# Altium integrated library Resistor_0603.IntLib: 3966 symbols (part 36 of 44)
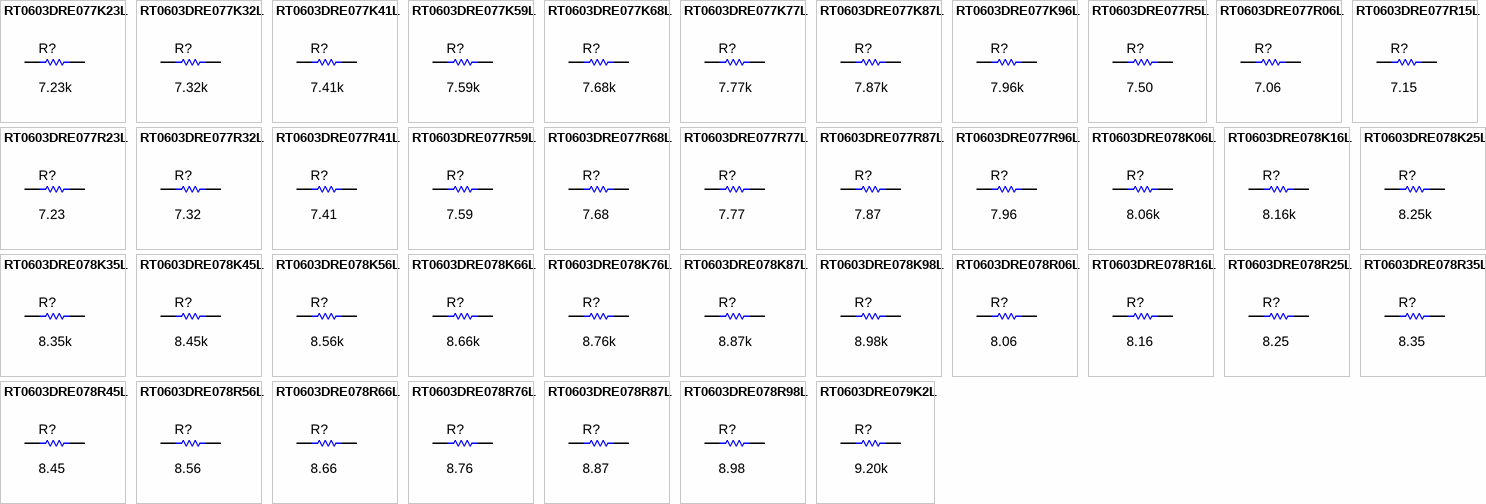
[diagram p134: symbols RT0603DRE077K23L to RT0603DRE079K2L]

## RT0603DRE078R87L
designator R?  ValueDisplayed: 8.87  (hidden comment: RT0603DRE078R87L)
RES, 8.87, 0.5%, 0.1 W, 0603; Manufacturer: Yageo America; CompType: Resistor; Value: 8.87; Value_Code: 8R87; Tolerance_%: 0.5; Power_W: 0.1; Value2: 0.1W; VDC_V: 75; TempCo: 50 ppm/C; SizeArea_mm2: 1.28; SizeX_mm: 1.6; SizeY_mm: 0.8; SizeZ_mm: 1; EIA_Code: E192; U/M: EA; AEC Category: Q200
signal-integrity model Resistor
simulation model Resistor
footprint 0603
footprint 0603M
footprint 0603L
footprint 0603_HV
footprint 0603S
pins: 1, 2

## RT0603DRE078R98L
designator R?  ValueDisplayed: 8.98  (hidden comment: RT0603DRE078R98L)
RES, 8.98, 0.5%, 0.1 W, 0603; Manufacturer: Yageo America; CompType: Resistor; Value: 8.98; Value_Code: 8R98; Tolerance_%: 0.5; Power_W: 0.1; Value2: 0.1W; VDC_V: 75; TempCo: 50 ppm/C; SizeArea_mm2: 1.28; SizeX_mm: 1.6; SizeY_mm: 0.8; SizeZ_mm: 1; EIA_Code: E192; U/M: EA; AEC Category: Q200
signal-integrity model Resistor
simulation model Resistor
footprint 0603
footprint 0603M
footprint 0603L
footprint 0603_HV
footprint 0603S
pins: 1, 2

## RT0603DRE079K2L
designator R?  ValueDisplayed: 9.20k  (hidden comment: RT0603DRE079K2L)
RES, 9.20 k, 0.5%, 0.1 W, 0603; Manufacturer: Yageo America; CompType: Resistor; Value: 9.20k; Res_ohm: 9200; Value_Code: 9k20; Tolerance_%: 0.5; Power_W: 0.1; Value2: 0.1W; VDC_V: 75; TempCo: 50 ppm/C; SizeArea_mm2: 1.28; SizeX_mm: 1.6; SizeY_mm: 0.8; SizeZ_mm: 1; EIA_Code: E192; U/M: EA; AEC Category: Q200
signal-integrity model Resistor
simulation model Resistor
footprint 0603
footprint 0603M
footprint 0603L
footprint 0603_HV
footprint 0603S
pins: 1, 2

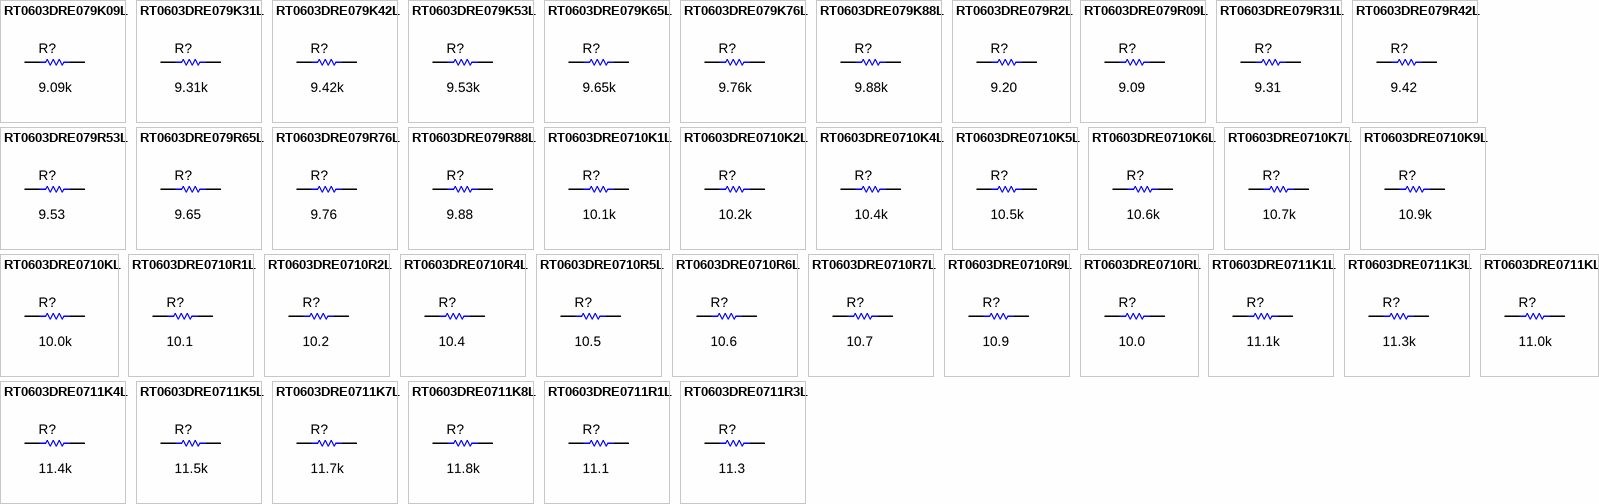
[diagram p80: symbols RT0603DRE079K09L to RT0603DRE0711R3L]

## RT0603DRE079K09L
designator R?  ValueDisplayed: 9.09k  (hidden comment: RT0603DRE079K09L)
RES, 9.09 k, 0.5%, 0.1 W, 0603; Manufacturer: Yageo America; CompType: Resistor; Value: 9.09k; Res_ohm: 9090; Value_Code: 9k09; Tolerance_%: 0.5; Power_W: 0.1; Value2: 0.1W; VDC_V: 75; TempCo: 50 ppm/C; SizeArea_mm2: 1.28; SizeX_mm: 1.6; SizeY_mm: 0.8; SizeZ_mm: 1; EIA_Code: E192; U/M: EA; AEC Category: Q200
signal-integrity model Resistor
simulation model Resistor
footprint 0603
footprint 0603M
footprint 0603L
footprint 0603_HV
footprint 0603S
pins: 1, 2

## RT0603DRE079K31L
designator R?  ValueDisplayed: 9.31k  (hidden comment: RT0603DRE079K31L)
RES, 9.31 k, 0.5%, 0.1 W, 0603; Manufacturer: Yageo America; CompType: Resistor; Value: 9.31k; Res_ohm: 9310; Value_Code: 9k31; Tolerance_%: 0.5; Power_W: 0.1; Value2: 0.1W; VDC_V: 75; TempCo: 50 ppm/C; SizeArea_mm2: 1.28; SizeX_mm: 1.6; SizeY_mm: 0.8; SizeZ_mm: 1; EIA_Code: E192; U/M: EA; AEC Category: Q200
signal-integrity model Resistor
simulation model Resistor
footprint 0603
footprint 0603M
footprint 0603L
footprint 0603_HV
footprint 0603S
pins: 1, 2

## RT0603DRE079K42L
designator R?  ValueDisplayed: 9.42k  (hidden comment: RT0603DRE079K42L)
RES, 9.42 k, 0.5%, 0.1 W, 0603; Manufacturer: Yageo America; CompType: Resistor; Value: 9.42k; Res_ohm: 9420; Value_Code: 9k42; Tolerance_%: 0.5; Power_W: 0.1; Value2: 0.1W; VDC_V: 75; TempCo: 50 ppm/C; SizeArea_mm2: 1.28; SizeX_mm: 1.6; SizeY_mm: 0.8; SizeZ_mm: 1; EIA_Code: E192; U/M: EA; AEC Category: Q200
signal-integrity model Resistor
simulation model Resistor
footprint 0603
footprint 0603M
footprint 0603L
footprint 0603_HV
footprint 0603S
pins: 1, 2

## RT0603DRE079K53L
designator R?  ValueDisplayed: 9.53k  (hidden comment: RT0603DRE079K53L)
RES, 9.53 k, 0.5%, 0.1 W, 0603; Manufacturer: Yageo America; CompType: Resistor; Value: 9.53k; Res_ohm: 9530; Value_Code: 9k53; Tolerance_%: 0.5; Power_W: 0.1; Value2: 0.1W; VDC_V: 75; TempCo: 50 ppm/C; SizeArea_mm2: 1.28; SizeX_mm: 1.6; SizeY_mm: 0.8; SizeZ_mm: 1; EIA_Code: E192; U/M: EA; AEC Category: Q200
signal-integrity model Resistor
simulation model Resistor
footprint 0603
footprint 0603M
footprint 0603L
footprint 0603_HV
footprint 0603S
pins: 1, 2

## RT0603DRE079K65L
designator R?  ValueDisplayed: 9.65k  (hidden comment: RT0603DRE079K65L)
RES, 9.65 k, 0.5%, 0.1 W, 0603; Manufacturer: Yageo America; CompType: Resistor; Value: 9.65k; Res_ohm: 9650; Value_Code: 9k65; Tolerance_%: 0.5; Power_W: 0.1; Value2: 0.1W; VDC_V: 75; TempCo: 50 ppm/C; SizeArea_mm2: 1.28; SizeX_mm: 1.6; SizeY_mm: 0.8; SizeZ_mm: 1; EIA_Code: E192; U/M: EA; AEC Category: Q200
signal-integrity model Resistor
simulation model Resistor
footprint 0603
footprint 0603M
footprint 0603L
footprint 0603_HV
footprint 0603S
pins: 1, 2

## RT0603DRE079K76L
designator R?  ValueDisplayed: 9.76k  (hidden comment: RT0603DRE079K76L)
RES, 9.76 k, 0.5%, 0.1 W, 0603; Manufacturer: Yageo America; CompType: Resistor; Value: 9.76k; Res_ohm: 9760; Value_Code: 9k76; Tolerance_%: 0.5; Power_W: 0.1; Value2: 0.1W; VDC_V: 75; TempCo: 50 ppm/C; SizeArea_mm2: 1.28; SizeX_mm: 1.6; SizeY_mm: 0.8; SizeZ_mm: 1; EIA_Code: E192; U/M: EA; AEC Category: Q200
signal-integrity model Resistor
simulation model Resistor
footprint 0603
footprint 0603M
footprint 0603L
footprint 0603_HV
footprint 0603S
pins: 1, 2

## RT0603DRE079K88L
designator R?  ValueDisplayed: 9.88k  (hidden comment: RT0603DRE079K88L)
RES, 9.88 k, 0.5%, 0.1 W, 0603; Manufacturer: Yageo America; CompType: Resistor; Value: 9.88k; Res_ohm: 9880; Value_Code: 9k88; Tolerance_%: 0.5; Power_W: 0.1; Value2: 0.1W; VDC_V: 75; TempCo: 50 ppm/C; SizeArea_mm2: 1.28; SizeX_mm: 1.6; SizeY_mm: 0.8; SizeZ_mm: 1; EIA_Code: E192; U/M: EA; AEC Category: Q200
signal-integrity model Resistor
simulation model Resistor
footprint 0603
footprint 0603M
footprint 0603L
footprint 0603_HV
footprint 0603S
pins: 1, 2

## RT0603DRE079R2L
designator R?  ValueDisplayed: 9.20  (hidden comment: RT0603DRE079R2L)
RES, 9.20, 0.5%, 0.1 W, 0603; Manufacturer: Yageo America; CompType: Resistor; Value: 9.20; Res_ohm: 9.2; Value_Code: 9R20; Tolerance_%: 0.5; Power_W: 0.1; Value2: 0.1W; VDC_V: 75; TempCo: 50 ppm/C; SizeArea_mm2: 1.28; SizeX_mm: 1.6; SizeY_mm: 0.8; SizeZ_mm: 1; EIA_Code: E192; U/M: EA; AEC Category: Q200
signal-integrity model Resistor
simulation model Resistor
footprint 0603
footprint 0603M
footprint 0603L
footprint 0603_HV
footprint 0603S
pins: 1, 2

## RT0603DRE079R09L
designator R?  ValueDisplayed: 9.09  (hidden comment: RT0603DRE079R09L)
RES, 9.09, 0.5%, 0.1 W, 0603; Manufacturer: Yageo America; CompType: Resistor; Value: 9.09; Value_Code: 9R09; Tolerance_%: 0.5; Power_W: 0.1; Value2: 0.1W; VDC_V: 75; TempCo: 50 ppm/C; SizeArea_mm2: 1.28; SizeX_mm: 1.6; SizeY_mm: 0.8; SizeZ_mm: 1; EIA_Code: E192; U/M: EA; AEC Category: Q200
signal-integrity model Resistor
simulation model Resistor
footprint 0603
footprint 0603M
footprint 0603L
footprint 0603_HV
footprint 0603S
pins: 1, 2

## RT0603DRE079R31L
designator R?  ValueDisplayed: 9.31  (hidden comment: RT0603DRE079R31L)
RES, 9.31, 0.5%, 0.1 W, 0603; Manufacturer: Yageo America; CompType: Resistor; Value: 9.31; Value_Code: 9R31; Tolerance_%: 0.5; Power_W: 0.1; Value2: 0.1W; VDC_V: 75; TempCo: 50 ppm/C; SizeArea_mm2: 1.28; SizeX_mm: 1.6; SizeY_mm: 0.8; SizeZ_mm: 1; EIA_Code: E192; U/M: EA; AEC Category: Q200
signal-integrity model Resistor
simulation model Resistor
footprint 0603
footprint 0603M
footprint 0603L
footprint 0603_HV
footprint 0603S
pins: 1, 2

## RT0603DRE079R42L
designator R?  ValueDisplayed: 9.42  (hidden comment: RT0603DRE079R42L)
RES, 9.42, 0.5%, 0.1 W, 0603; Manufacturer: Yageo America; CompType: Resistor; Value: 9.42; Value_Code: 9R42; Tolerance_%: 0.5; Power_W: 0.1; Value2: 0.1W; VDC_V: 75; TempCo: 50 ppm/C; SizeArea_mm2: 1.28; SizeX_mm: 1.6; SizeY_mm: 0.8; SizeZ_mm: 1; EIA_Code: E192; U/M: EA; AEC Category: Q200
signal-integrity model Resistor
simulation model Resistor
footprint 0603
footprint 0603M
footprint 0603L
footprint 0603_HV
footprint 0603S
pins: 1, 2

## RT0603DRE079R53L
designator R?  ValueDisplayed: 9.53  (hidden comment: RT0603DRE079R53L)
RES, 9.53, 0.5%, 0.1 W, 0603; Manufacturer: Yageo America; CompType: Resistor; Value: 9.53; Value_Code: 9R53; Tolerance_%: 0.5; Power_W: 0.1; Value2: 0.1W; VDC_V: 75; TempCo: 50 ppm/C; SizeArea_mm2: 1.28; SizeX_mm: 1.6; SizeY_mm: 0.8; SizeZ_mm: 1; EIA_Code: E192; U/M: EA; AEC Category: Q200
signal-integrity model Resistor
simulation model Resistor
footprint 0603
footprint 0603M
footprint 0603L
footprint 0603_HV
footprint 0603S
pins: 1, 2

## RT0603DRE079R65L
designator R?  ValueDisplayed: 9.65  (hidden comment: RT0603DRE079R65L)
RES, 9.65, 0.5%, 0.1 W, 0603; Manufacturer: Yageo America; CompType: Resistor; Value: 9.65; Value_Code: 9R65; Tolerance_%: 0.5; Power_W: 0.1; Value2: 0.1W; VDC_V: 75; TempCo: 50 ppm/C; SizeArea_mm2: 1.28; SizeX_mm: 1.6; SizeY_mm: 0.8; SizeZ_mm: 1; EIA_Code: E192; U/M: EA; AEC Category: Q200
signal-integrity model Resistor
simulation model Resistor
footprint 0603
footprint 0603M
footprint 0603L
footprint 0603_HV
footprint 0603S
pins: 1, 2

## RT0603DRE079R76L
designator R?  ValueDisplayed: 9.76  (hidden comment: RT0603DRE079R76L)
RES, 9.76, 0.5%, 0.1 W, 0603; Manufacturer: Yageo America; CompType: Resistor; Value: 9.76; Value_Code: 9R76; Tolerance_%: 0.5; Power_W: 0.1; Value2: 0.1W; VDC_V: 75; TempCo: 50 ppm/C; SizeArea_mm2: 1.28; SizeX_mm: 1.6; SizeY_mm: 0.8; SizeZ_mm: 1; EIA_Code: E192; U/M: EA; AEC Category: Q200
signal-integrity model Resistor
simulation model Resistor
footprint 0603
footprint 0603M
footprint 0603L
footprint 0603_HV
footprint 0603S
pins: 1, 2

## RT0603DRE079R88L
designator R?  ValueDisplayed: 9.88  (hidden comment: RT0603DRE079R88L)
RES, 9.88, 0.5%, 0.1 W, 0603; Manufacturer: Yageo America; CompType: Resistor; Value: 9.88; Value_Code: 9R88; Tolerance_%: 0.5; Power_W: 0.1; Value2: 0.1W; VDC_V: 75; TempCo: 50 ppm/C; SizeArea_mm2: 1.28; SizeX_mm: 1.6; SizeY_mm: 0.8; SizeZ_mm: 1; EIA_Code: E192; U/M: EA; AEC Category: Q200
signal-integrity model Resistor
simulation model Resistor
footprint 0603
footprint 0603M
footprint 0603L
footprint 0603_HV
footprint 0603S
pins: 1, 2

## RT0603DRE0710K1L
designator R?  ValueDisplayed: 10.1k  (hidden comment: RT0603DRE0710K1L)
RES, 10.1 k, 0.5%, 0.1 W, 0603; Manufacturer: Yageo America; CompType: Resistor; Value: 10.1k; Res_ohm: 10100; Value_Code: 10k1; Tolerance_%: 0.5; Power_W: 0.1; Value2: 0.1W; VDC_V: 75; TempCo: 50 ppm/C; SizeArea_mm2: 1.28; SizeX_mm: 1.6; SizeY_mm: 0.8; SizeZ_mm: 1; EIA_Code: E192; U/M: EA; AEC Category: Q200
signal-integrity model Resistor
simulation model Resistor
footprint 0603
footprint 0603M
footprint 0603L
footprint 0603_HV
footprint 0603S
pins: 1, 2

## RT0603DRE0710K2L
designator R?  ValueDisplayed: 10.2k  (hidden comment: RT0603DRE0710K2L)
RES, 10.2 k, 0.5%, 0.1 W, 0603; Manufacturer: Yageo America; CompType: Resistor; Value: 10.2k; Res_ohm: 10200; Value_Code: 10k2; Tolerance_%: 0.5; Power_W: 0.1; Value2: 0.1W; VDC_V: 75; TempCo: 50 ppm/C; SizeArea_mm2: 1.28; SizeX_mm: 1.6; SizeY_mm: 0.8; SizeZ_mm: 1; EIA_Code: E192; U/M: EA; AEC Category: Q200
signal-integrity model Resistor
simulation model Resistor
footprint 0603
footprint 0603M
footprint 0603L
footprint 0603_HV
footprint 0603S
pins: 1, 2

## RT0603DRE0710K4L
designator R?  ValueDisplayed: 10.4k  (hidden comment: RT0603DRE0710K4L)
RES, 10.4 k, 0.5%, 0.1 W, 0603; Manufacturer: Yageo America; CompType: Resistor; Value: 10.4k; Res_ohm: 10400; Value_Code: 10k4; Tolerance_%: 0.5; Power_W: 0.1; Value2: 0.1W; VDC_V: 75; TempCo: 50 ppm/C; SizeArea_mm2: 1.28; SizeX_mm: 1.6; SizeY_mm: 0.8; SizeZ_mm: 1; EIA_Code: E192; U/M: EA; AEC Category: Q200
signal-integrity model Resistor
simulation model Resistor
footprint 0603
footprint 0603M
footprint 0603L
footprint 0603_HV
footprint 0603S
pins: 1, 2

## RT0603DRE0710K5L
designator R?  ValueDisplayed: 10.5k  (hidden comment: RT0603DRE0710K5L)
RES, 10.5 k, 0.5%, 0.1 W, 0603; Manufacturer: Yageo America; CompType: Resistor; Value: 10.5k; Res_ohm: 10500; Value_Code: 10k5; Tolerance_%: 0.5; Power_W: 0.1; Value2: 0.1W; VDC_V: 75; TempCo: 50 ppm/C; SizeArea_mm2: 1.28; SizeX_mm: 1.6; SizeY_mm: 0.8; SizeZ_mm: 1; EIA_Code: E192; U/M: EA; AEC Category: Q200
signal-integrity model Resistor
simulation model Resistor
footprint 0603
footprint 0603M
footprint 0603L
footprint 0603_HV
footprint 0603S
pins: 1, 2

## RT0603DRE0710K6L
designator R?  ValueDisplayed: 10.6k  (hidden comment: RT0603DRE0710K6L)
RES, 10.6 k, 0.5%, 0.1 W, 0603; Manufacturer: Yageo America; CompType: Resistor; Value: 10.6k; Res_ohm: 10600; Value_Code: 10k6; Tolerance_%: 0.5; Power_W: 0.1; Value2: 0.1W; VDC_V: 75; TempCo: 50 ppm/C; SizeArea_mm2: 1.28; SizeX_mm: 1.6; SizeY_mm: 0.8; SizeZ_mm: 1; EIA_Code: E192; U/M: EA; AEC Category: Q200
signal-integrity model Resistor
simulation model Resistor
footprint 0603
footprint 0603M
footprint 0603L
footprint 0603_HV
footprint 0603S
pins: 1, 2

## RT0603DRE0710K7L
designator R?  ValueDisplayed: 10.7k  (hidden comment: RT0603DRE0710K7L)
RES, 10.7 k, 0.5%, 0.1 W, 0603; Manufacturer: Yageo America; CompType: Resistor; Value: 10.7k; Res_ohm: 10700; Value_Code: 10k7; Tolerance_%: 0.5; Power_W: 0.1; Value2: 0.1W; VDC_V: 75; TempCo: 50 ppm/C; SizeArea_mm2: 1.28; SizeX_mm: 1.6; SizeY_mm: 0.8; SizeZ_mm: 1; EIA_Code: E192; U/M: EA; AEC Category: Q200
signal-integrity model Resistor
simulation model Resistor
footprint 0603
footprint 0603M
footprint 0603L
footprint 0603_HV
footprint 0603S
pins: 1, 2

## RT0603DRE0710K9L
designator R?  ValueDisplayed: 10.9k  (hidden comment: RT0603DRE0710K9L)
RES, 10.9 k, 0.5%, 0.1 W, 0603; Manufacturer: Yageo America; CompType: Resistor; Value: 10.9k; Res_ohm: 10900; Value_Code: 10k9; Tolerance_%: 0.5; Power_W: 0.1; Value2: 0.1W; VDC_V: 75; TempCo: 50 ppm/C; SizeArea_mm2: 1.28; SizeX_mm: 1.6; SizeY_mm: 0.8; SizeZ_mm: 1; EIA_Code: E192; U/M: EA; AEC Category: Q200
signal-integrity model Resistor
simulation model Resistor
footprint 0603
footprint 0603M
footprint 0603L
footprint 0603_HV
footprint 0603S
pins: 1, 2

## RT0603DRE0710KL
designator R?  ValueDisplayed: 10.0k  (hidden comment: RT0603DRE0710KL)
RES, 10.0 k, 0.5%, 0.1 W, 0603; Manufacturer: Yageo America; CompType: Resistor; Value: 10.0k; Res_ohm: 10000; Value_Code: 10k0; Tolerance_%: 0.5; Power_W: 0.1; Value2: 0.1W; VDC_V: 75; TempCo: 50 ppm/C; SizeArea_mm2: 1.28; SizeX_mm: 1.6; SizeY_mm: 0.8; SizeZ_mm: 1; EIA_Code: E192; U/M: EA; AEC Category: Q200; Green_Lifecycle: Active; Green_REACh: Passed
signal-integrity model Resistor
simulation model Resistor
footprint 0603
footprint 0603M
footprint 0603L
footprint 0603_HV
footprint 0603S
pins: 1, 2

## RT0603DRE0710R1L
designator R?  ValueDisplayed: 10.1  (hidden comment: RT0603DRE0710R1L)
RES, 10.1, 0.5%, 0.1 W, 0603; Manufacturer: Yageo America; CompType: Resistor; Value: 10.1; Value_Code: 10R1; Tolerance_%: 0.5; Power_W: 0.1; Value2: 0.1W; VDC_V: 75; TempCo: 50 ppm/C; SizeArea_mm2: 1.28; SizeX_mm: 1.6; SizeY_mm: 0.8; SizeZ_mm: 1; EIA_Code: E192; U/M: EA; AEC Category: Q200
signal-integrity model Resistor
simulation model Resistor
footprint 0603
footprint 0603M
footprint 0603L
footprint 0603_HV
footprint 0603S
pins: 1, 2

## RT0603DRE0710R2L
designator R?  ValueDisplayed: 10.2  (hidden comment: RT0603DRE0710R2L)
RES, 10.2, 0.5%, 0.1 W, 0603; Manufacturer: Yageo America; CompType: Resistor; Value: 10.2; Value_Code: 10R2; Tolerance_%: 0.5; Power_W: 0.1; Value2: 0.1W; VDC_V: 75; TempCo: 50 ppm/C; SizeArea_mm2: 1.28; SizeX_mm: 1.6; SizeY_mm: 0.8; SizeZ_mm: 1; EIA_Code: E192; U/M: EA; AEC Category: Q200
signal-integrity model Resistor
simulation model Resistor
footprint 0603
footprint 0603M
footprint 0603L
footprint 0603_HV
footprint 0603S
pins: 1, 2

## RT0603DRE0710R4L
designator R?  ValueDisplayed: 10.4  (hidden comment: RT0603DRE0710R4L)
RES, 10.4, 0.5%, 0.1 W, 0603; Manufacturer: Yageo America; CompType: Resistor; Value: 10.4; Value_Code: 10R4; Tolerance_%: 0.5; Power_W: 0.1; Value2: 0.1W; VDC_V: 75; TempCo: 50 ppm/C; SizeArea_mm2: 1.28; SizeX_mm: 1.6; SizeY_mm: 0.8; SizeZ_mm: 1; EIA_Code: E192; U/M: EA; AEC Category: Q200
signal-integrity model Resistor
simulation model Resistor
footprint 0603
footprint 0603M
footprint 0603L
footprint 0603_HV
footprint 0603S
pins: 1, 2

## RT0603DRE0710R5L
designator R?  ValueDisplayed: 10.5  (hidden comment: RT0603DRE0710R5L)
RES, 10.5, 0.5%, 0.1 W, 0603; Manufacturer: Yageo America; CompType: Resistor; Value: 10.5; Value_Code: 10R5; Tolerance_%: 0.5; Power_W: 0.1; Value2: 0.1W; VDC_V: 75; TempCo: 50 ppm/C; SizeArea_mm2: 1.28; SizeX_mm: 1.6; SizeY_mm: 0.8; SizeZ_mm: 1; EIA_Code: E192; U/M: EA; AEC Category: Q200
signal-integrity model Resistor
simulation model Resistor
footprint 0603
footprint 0603M
footprint 0603L
footprint 0603_HV
footprint 0603S
pins: 1, 2

## RT0603DRE0710R6L
designator R?  ValueDisplayed: 10.6  (hidden comment: RT0603DRE0710R6L)
RES, 10.6, 0.5%, 0.1 W, 0603; Manufacturer: Yageo America; CompType: Resistor; Value: 10.6; Value_Code: 10R6; Tolerance_%: 0.5; Power_W: 0.1; Value2: 0.1W; VDC_V: 75; TempCo: 50 ppm/C; SizeArea_mm2: 1.28; SizeX_mm: 1.6; SizeY_mm: 0.8; SizeZ_mm: 1; EIA_Code: E192; U/M: EA; AEC Category: Q200
signal-integrity model Resistor
simulation model Resistor
footprint 0603
footprint 0603M
footprint 0603L
footprint 0603_HV
footprint 0603S
pins: 1, 2

## RT0603DRE0710R7L
designator R?  ValueDisplayed: 10.7  (hidden comment: RT0603DRE0710R7L)
RES, 10.7, 0.5%, 0.1 W, 0603; Manufacturer: Yageo America; CompType: Resistor; Value: 10.7; Value_Code: 10R7; Tolerance_%: 0.5; Power_W: 0.1; Value2: 0.1W; VDC_V: 75; TempCo: 50 ppm/C; SizeArea_mm2: 1.28; SizeX_mm: 1.6; SizeY_mm: 0.8; SizeZ_mm: 1; EIA_Code: E192; U/M: EA; AEC Category: Q200
signal-integrity model Resistor
simulation model Resistor
footprint 0603
footprint 0603M
footprint 0603L
footprint 0603_HV
footprint 0603S
pins: 1, 2

## RT0603DRE0710R9L
designator R?  ValueDisplayed: 10.9  (hidden comment: RT0603DRE0710R9L)
RES, 10.9, 0.5%, 0.1 W, 0603; Manufacturer: Yageo America; CompType: Resistor; Value: 10.9; Value_Code: 10R9; Tolerance_%: 0.5; Power_W: 0.1; Value2: 0.1W; VDC_V: 75; TempCo: 50 ppm/C; SizeArea_mm2: 1.28; SizeX_mm: 1.6; SizeY_mm: 0.8; SizeZ_mm: 1; EIA_Code: E192; U/M: EA; AEC Category: Q200
signal-integrity model Resistor
simulation model Resistor
footprint 0603
footprint 0603M
footprint 0603L
footprint 0603_HV
footprint 0603S
pins: 1, 2

## RT0603DRE0710RL
designator R?  ValueDisplayed: 10.0  (hidden comment: RT0603DRE0710RL)
RES, 10.0, 0.5%, 0.1 W, 0603; Manufacturer: Yageo America; CompType: Resistor; Value: 10.0; Res_ohm: 10; Value_Code: 10R0; Tolerance_%: 0.5; Power_W: 0.1; Value2: 0.1W; VDC_V: 75; TempCo: 50 ppm/C; SizeArea_mm2: 1.28; SizeX_mm: 1.6; SizeY_mm: 0.8; SizeZ_mm: 1; EIA_Code: E192; U/M: EA; AEC Category: Q200
signal-integrity model Resistor
simulation model Resistor
footprint 0603
footprint 0603M
footprint 0603L
footprint 0603_HV
footprint 0603S
pins: 1, 2

## RT0603DRE0711K1L
designator R?  ValueDisplayed: 11.1k  (hidden comment: RT0603DRE0711K1L)
RES, 11.1 k, 0.5%, 0.1 W, 0603; Manufacturer: Yageo America; CompType: Resistor; Value: 11.1k; Res_ohm: 11100; Value_Code: 11k1; Tolerance_%: 0.5; Power_W: 0.1; Value2: 0.1W; VDC_V: 75; TempCo: 50 ppm/C; SizeArea_mm2: 1.28; SizeX_mm: 1.6; SizeY_mm: 0.8; SizeZ_mm: 1; EIA_Code: E192; U/M: EA; AEC Category: Q200
signal-integrity model Resistor
simulation model Resistor
footprint 0603
footprint 0603M
footprint 0603L
footprint 0603_HV
footprint 0603S
pins: 1, 2

## RT0603DRE0711K3L
designator R?  ValueDisplayed: 11.3k  (hidden comment: RT0603DRE0711K3L)
RES, 11.3 k, 0.5%, 0.1 W, 0603; Manufacturer: Yageo America; CompType: Resistor; Value: 11.3k; Res_ohm: 11300; Value_Code: 11k3; Tolerance_%: 0.5; Power_W: 0.1; Value2: 0.1W; VDC_V: 75; TempCo: 50 ppm/C; SizeArea_mm2: 1.28; SizeX_mm: 1.6; SizeY_mm: 0.8; SizeZ_mm: 1; EIA_Code: E192; U/M: EA; AEC Category: Q200
signal-integrity model Resistor
simulation model Resistor
footprint 0603
footprint 0603M
footprint 0603L
footprint 0603_HV
footprint 0603S
pins: 1, 2

## RT0603DRE0711K4L
designator R?  ValueDisplayed: 11.4k  (hidden comment: RT0603DRE0711K4L)
RES, 11.4 k, 0.5%, 0.1 W, 0603; Manufacturer: Yageo America; CompType: Resistor; Value: 11.4k; Res_ohm: 11400; Value_Code: 11k4; Tolerance_%: 0.5; Power_W: 0.1; Value2: 0.1W; VDC_V: 75; TempCo: 50 ppm/C; SizeArea_mm2: 1.28; SizeX_mm: 1.6; SizeY_mm: 0.8; SizeZ_mm: 1; EIA_Code: E192; U/M: EA; AEC Category: Q200
signal-integrity model Resistor
simulation model Resistor
footprint 0603
footprint 0603M
footprint 0603L
footprint 0603_HV
footprint 0603S
pins: 1, 2

## RT0603DRE0711K5L
designator R?  ValueDisplayed: 11.5k  (hidden comment: RT0603DRE0711K5L)
RES, 11.5 k, 0.5%, 0.1 W, 0603; Manufacturer: Yageo America; CompType: Resistor; Value: 11.5k; Res_ohm: 11500; Value_Code: 11k5; Tolerance_%: 0.5; Power_W: 0.1; Value2: 0.1W; VDC_V: 75; TempCo: 50 ppm/C; SizeArea_mm2: 1.28; SizeX_mm: 1.6; SizeY_mm: 0.8; SizeZ_mm: 1; EIA_Code: E192; U/M: EA; AEC Category: Q200
signal-integrity model Resistor
simulation model Resistor
footprint 0603
footprint 0603M
footprint 0603L
footprint 0603_HV
footprint 0603S
pins: 1, 2

## RT0603DRE0711K7L
designator R?  ValueDisplayed: 11.7k  (hidden comment: RT0603DRE0711K7L)
RES, 11.7 k, 0.5%, 0.1 W, 0603; Manufacturer: Yageo America; CompType: Resistor; Value: 11.7k; Res_ohm: 11700; Value_Code: 11k7; Tolerance_%: 0.5; Power_W: 0.1; Value2: 0.1W; VDC_V: 75; TempCo: 50 ppm/C; SizeArea_mm2: 1.28; SizeX_mm: 1.6; SizeY_mm: 0.8; SizeZ_mm: 1; EIA_Code: E192; U/M: EA; AEC Category: Q200
signal-integrity model Resistor
simulation model Resistor
footprint 0603
footprint 0603M
footprint 0603L
footprint 0603_HV
footprint 0603S
pins: 1, 2

## RT0603DRE0711K8L
designator R?  ValueDisplayed: 11.8k  (hidden comment: RT0603DRE0711K8L)
RES, 11.8 k, 0.5%, 0.1 W, 0603; Manufacturer: Yageo America; CompType: Resistor; Value: 11.8k; Res_ohm: 11800; Value_Code: 11k8; Tolerance_%: 0.5; Power_W: 0.1; Value2: 0.1W; VDC_V: 75; TempCo: 50 ppm/C; SizeArea_mm2: 1.28; SizeX_mm: 1.6; SizeY_mm: 0.8; SizeZ_mm: 1; EIA_Code: E192; U/M: EA; AEC Category: Q200
signal-integrity model Resistor
simulation model Resistor
footprint 0603
footprint 0603M
footprint 0603L
footprint 0603_HV
footprint 0603S
pins: 1, 2

## RT0603DRE0711KL
designator R?  ValueDisplayed: 11.0k  (hidden comment: RT0603DRE0711KL)
RES, 11.0 k, 0.5%, 0.1 W, 0603; Manufacturer: Yageo America; CompType: Resistor; Value: 11.0k; Res_ohm: 11000; Value_Code: 11k0; Tolerance_%: 0.5; Power_W: 0.1; Value2: 0.1W; VDC_V: 75; TempCo: 50 ppm/C; SizeArea_mm2: 1.28; SizeX_mm: 1.6; SizeY_mm: 0.8; SizeZ_mm: 1; EIA_Code: E192; U/M: EA; AEC Category: Q200
signal-integrity model Resistor
simulation model Resistor
footprint 0603
footprint 0603M
footprint 0603L
footprint 0603_HV
footprint 0603S
pins: 1, 2

## RT0603DRE0711R1L
designator R?  ValueDisplayed: 11.1  (hidden comment: RT0603DRE0711R1L)
RES, 11.1, 0.5%, 0.1 W, 0603; Manufacturer: Yageo America; CompType: Resistor; Value: 11.1; Value_Code: 11R1; Tolerance_%: 0.5; Power_W: 0.1; Value2: 0.1W; VDC_V: 75; TempCo: 50 ppm/C; SizeArea_mm2: 1.28; SizeX_mm: 1.6; SizeY_mm: 0.8; SizeZ_mm: 1; EIA_Code: E192; U/M: EA; AEC Category: Q200
signal-integrity model Resistor
simulation model Resistor
footprint 0603
footprint 0603M
footprint 0603L
footprint 0603_HV
footprint 0603S
pins: 1, 2

## RT0603DRE0711R3L
designator R?  ValueDisplayed: 11.3  (hidden comment: RT0603DRE0711R3L)
RES, 11.3, 0.5%, 0.1 W, 0603; Manufacturer: Yageo America; CompType: Resistor; Value: 11.3; Value_Code: 11R3; Tolerance_%: 0.5; Power_W: 0.1; Value2: 0.1W; VDC_V: 75; TempCo: 50 ppm/C; SizeArea_mm2: 1.28; SizeX_mm: 1.6; SizeY_mm: 0.8; SizeZ_mm: 1; EIA_Code: E192; U/M: EA; AEC Category: Q200
signal-integrity model Resistor
simulation model Resistor
footprint 0603
footprint 0603M
footprint 0603L
footprint 0603_HV
footprint 0603S
pins: 1, 2

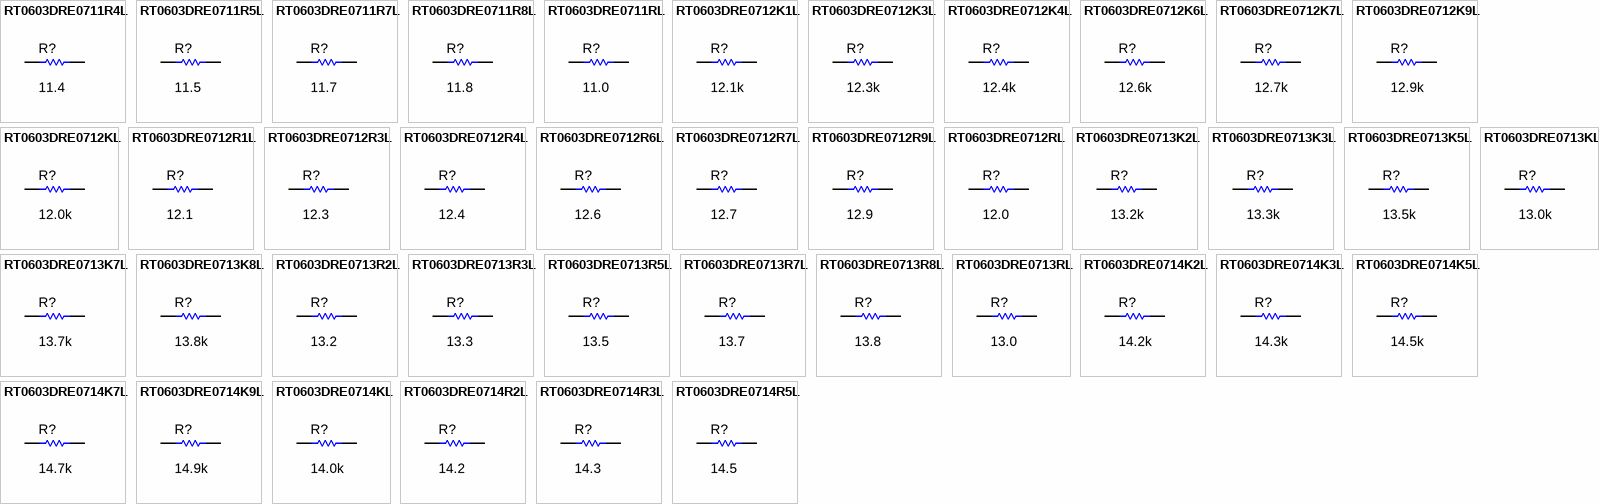
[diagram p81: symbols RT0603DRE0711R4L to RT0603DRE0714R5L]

## RT0603DRE0711R4L
designator R?  ValueDisplayed: 11.4  (hidden comment: RT0603DRE0711R4L)
RES, 11.4, 0.5%, 0.1 W, 0603; Manufacturer: Yageo America; CompType: Resistor; Value: 11.4; Value_Code: 11R4; Tolerance_%: 0.5; Power_W: 0.1; Value2: 0.1W; VDC_V: 75; TempCo: 50 ppm/C; SizeArea_mm2: 1.28; SizeX_mm: 1.6; SizeY_mm: 0.8; SizeZ_mm: 1; EIA_Code: E192; U/M: EA; AEC Category: Q200
signal-integrity model Resistor
simulation model Resistor
footprint 0603
footprint 0603M
footprint 0603L
footprint 0603_HV
footprint 0603S
pins: 1, 2

## RT0603DRE0711R5L
designator R?  ValueDisplayed: 11.5  (hidden comment: RT0603DRE0711R5L)
RES, 11.5, 0.5%, 0.1 W, 0603; Manufacturer: Yageo America; CompType: Resistor; Value: 11.5; Value_Code: 11R5; Tolerance_%: 0.5; Power_W: 0.1; Value2: 0.1W; VDC_V: 75; TempCo: 50 ppm/C; SizeArea_mm2: 1.28; SizeX_mm: 1.6; SizeY_mm: 0.8; SizeZ_mm: 1; EIA_Code: E192; U/M: EA; AEC Category: Q200
signal-integrity model Resistor
simulation model Resistor
footprint 0603
footprint 0603M
footprint 0603L
footprint 0603_HV
footprint 0603S
pins: 1, 2

## RT0603DRE0711R7L
designator R?  ValueDisplayed: 11.7  (hidden comment: RT0603DRE0711R7L)
RES, 11.7, 0.5%, 0.1 W, 0603; Manufacturer: Yageo America; CompType: Resistor; Value: 11.7; Value_Code: 11R7; Tolerance_%: 0.5; Power_W: 0.1; Value2: 0.1W; VDC_V: 75; TempCo: 50 ppm/C; SizeArea_mm2: 1.28; SizeX_mm: 1.6; SizeY_mm: 0.8; SizeZ_mm: 1; EIA_Code: E192; U/M: EA; AEC Category: Q200
signal-integrity model Resistor
simulation model Resistor
footprint 0603
footprint 0603M
footprint 0603L
footprint 0603_HV
footprint 0603S
pins: 1, 2

## RT0603DRE0711R8L
designator R?  ValueDisplayed: 11.8  (hidden comment: RT0603DRE0711R8L)
RES, 11.8, 0.5%, 0.1 W, 0603; Manufacturer: Yageo America; CompType: Resistor; Value: 11.8; Value_Code: 11R8; Tolerance_%: 0.5; Power_W: 0.1; Value2: 0.1W; VDC_V: 75; TempCo: 50 ppm/C; SizeArea_mm2: 1.28; SizeX_mm: 1.6; SizeY_mm: 0.8; SizeZ_mm: 1; EIA_Code: E192; U/M: EA; AEC Category: Q200
signal-integrity model Resistor
simulation model Resistor
footprint 0603
footprint 0603M
footprint 0603L
footprint 0603_HV
footprint 0603S
pins: 1, 2

## RT0603DRE0711RL
designator R?  ValueDisplayed: 11.0  (hidden comment: RT0603DRE0711RL)
RES, 11.0, 0.5%, 0.1 W, 0603; Manufacturer: Yageo America; CompType: Resistor; Value: 11.0; Res_ohm: 11; Value_Code: 11R0; Tolerance_%: 0.5; Power_W: 0.1; Value2: 0.1W; VDC_V: 75; TempCo: 50 ppm/C; SizeArea_mm2: 1.28; SizeX_mm: 1.6; SizeY_mm: 0.8; SizeZ_mm: 1; EIA_Code: E192; U/M: EA; AEC Category: Q200
signal-integrity model Resistor
simulation model Resistor
footprint 0603
footprint 0603M
footprint 0603L
footprint 0603_HV
footprint 0603S
pins: 1, 2

## RT0603DRE0712K1L
designator R?  ValueDisplayed: 12.1k  (hidden comment: RT0603DRE0712K1L)
RES, 12.1 k, 0.5%, 0.1 W, 0603; Manufacturer: Yageo America; CompType: Resistor; Value: 12.1k; Res_ohm: 12100; Value_Code: 12k1; Tolerance_%: 0.5; Power_W: 0.1; Value2: 0.1W; VDC_V: 75; TempCo: 50 ppm/C; SizeArea_mm2: 1.28; SizeX_mm: 1.6; SizeY_mm: 0.8; SizeZ_mm: 1; EIA_Code: E192; U/M: EA; AEC Category: Q200
signal-integrity model Resistor
simulation model Resistor
footprint 0603
footprint 0603M
footprint 0603L
footprint 0603_HV
footprint 0603S
pins: 1, 2

## RT0603DRE0712K3L
designator R?  ValueDisplayed: 12.3k  (hidden comment: RT0603DRE0712K3L)
RES, 12.3 k, 0.5%, 0.1 W, 0603; Manufacturer: Yageo America; CompType: Resistor; Value: 12.3k; Res_ohm: 12300; Value_Code: 12k3; Tolerance_%: 0.5; Power_W: 0.1; Value2: 0.1W; VDC_V: 75; TempCo: 50 ppm/C; SizeArea_mm2: 1.28; SizeX_mm: 1.6; SizeY_mm: 0.8; SizeZ_mm: 1; EIA_Code: E192; U/M: EA; AEC Category: Q200
signal-integrity model Resistor
simulation model Resistor
footprint 0603
footprint 0603M
footprint 0603L
footprint 0603_HV
footprint 0603S
pins: 1, 2

## RT0603DRE0712K4L
designator R?  ValueDisplayed: 12.4k  (hidden comment: RT0603DRE0712K4L)
RES, 12.4 k, 0.5%, 0.1 W, 0603; Manufacturer: Yageo America; CompType: Resistor; Value: 12.4k; Res_ohm: 12400; Value_Code: 12k4; Tolerance_%: 0.5; Power_W: 0.1; Value2: 0.1W; VDC_V: 75; TempCo: 50 ppm/C; SizeArea_mm2: 1.28; SizeX_mm: 1.6; SizeY_mm: 0.8; SizeZ_mm: 1; EIA_Code: E192; U/M: EA; AEC Category: Q200
signal-integrity model Resistor
simulation model Resistor
footprint 0603
footprint 0603M
footprint 0603L
footprint 0603_HV
footprint 0603S
pins: 1, 2

## RT0603DRE0712K6L
designator R?  ValueDisplayed: 12.6k  (hidden comment: RT0603DRE0712K6L)
RES, 12.6 k, 0.5%, 0.1 W, 0603; Manufacturer: Yageo America; CompType: Resistor; Value: 12.6k; Res_ohm: 12600; Value_Code: 12k6; Tolerance_%: 0.5; Power_W: 0.1; Value2: 0.1W; VDC_V: 75; TempCo: 50 ppm/C; SizeArea_mm2: 1.28; SizeX_mm: 1.6; SizeY_mm: 0.8; SizeZ_mm: 1; EIA_Code: E192; U/M: EA; AEC Category: Q200
signal-integrity model Resistor
simulation model Resistor
footprint 0603
footprint 0603M
footprint 0603L
footprint 0603_HV
footprint 0603S
pins: 1, 2

## RT0603DRE0712K7L
designator R?  ValueDisplayed: 12.7k  (hidden comment: RT0603DRE0712K7L)
RES, 12.7 k, 0.5%, 0.1 W, 0603; Manufacturer: Yageo America; CompType: Resistor; Value: 12.7k; Res_ohm: 12700; Value_Code: 12k7; Tolerance_%: 0.5; Power_W: 0.1; Value2: 0.1W; VDC_V: 75; TempCo: 50 ppm/C; SizeArea_mm2: 1.28; SizeX_mm: 1.6; SizeY_mm: 0.8; SizeZ_mm: 1; EIA_Code: E192; U/M: EA; AEC Category: Q200
signal-integrity model Resistor
simulation model Resistor
footprint 0603
footprint 0603M
footprint 0603L
footprint 0603_HV
footprint 0603S
pins: 1, 2

## RT0603DRE0712K9L
designator R?  ValueDisplayed: 12.9k  (hidden comment: RT0603DRE0712K9L)
RES, 12.9 k, 0.5%, 0.1 W, 0603; Manufacturer: Yageo America; CompType: Resistor; Value: 12.9k; Res_ohm: 12900; Value_Code: 12k9; Tolerance_%: 0.5; Power_W: 0.1; Value2: 0.1W; VDC_V: 75; TempCo: 50 ppm/C; SizeArea_mm2: 1.28; SizeX_mm: 1.6; SizeY_mm: 0.8; SizeZ_mm: 1; EIA_Code: E192; U/M: EA; AEC Category: Q200
signal-integrity model Resistor
simulation model Resistor
footprint 0603
footprint 0603M
footprint 0603L
footprint 0603_HV
footprint 0603S
pins: 1, 2

## RT0603DRE0712KL
designator R?  ValueDisplayed: 12.0k  (hidden comment: RT0603DRE0712KL)
RES, 12.0 k, 0.5%, 0.1 W, 0603; Manufacturer: Yageo America; CompType: Resistor; Value: 12.0k; Res_ohm: 12000; Value_Code: 12k0; Tolerance_%: 0.5; Power_W: 0.1; Value2: 0.1W; VDC_V: 75; TempCo: 50 ppm/C; SizeArea_mm2: 1.28; SizeX_mm: 1.6; SizeY_mm: 0.8; SizeZ_mm: 1; EIA_Code: E192; U/M: EA; AEC Category: Q200
signal-integrity model Resistor
simulation model Resistor
footprint 0603
footprint 0603M
footprint 0603L
footprint 0603_HV
footprint 0603S
pins: 1, 2

## RT0603DRE0712R1L
designator R?  ValueDisplayed: 12.1  (hidden comment: RT0603DRE0712R1L)
RES, 12.1, 0.5%, 0.1 W, 0603; Manufacturer: Yageo America; CompType: Resistor; Value: 12.1; Value_Code: 12R1; Tolerance_%: 0.5; Power_W: 0.1; Value2: 0.1W; VDC_V: 75; TempCo: 50 ppm/C; SizeArea_mm2: 1.28; SizeX_mm: 1.6; SizeY_mm: 0.8; SizeZ_mm: 1; EIA_Code: E192; U/M: EA; AEC Category: Q200
signal-integrity model Resistor
simulation model Resistor
footprint 0603
footprint 0603M
footprint 0603L
footprint 0603_HV
footprint 0603S
pins: 1, 2

## RT0603DRE0712R3L
designator R?  ValueDisplayed: 12.3  (hidden comment: RT0603DRE0712R3L)
RES, 12.3, 0.5%, 0.1 W, 0603; Manufacturer: Yageo America; CompType: Resistor; Value: 12.3; Value_Code: 12R3; Tolerance_%: 0.5; Power_W: 0.1; Value2: 0.1W; VDC_V: 75; TempCo: 50 ppm/C; SizeArea_mm2: 1.28; SizeX_mm: 1.6; SizeY_mm: 0.8; SizeZ_mm: 1; EIA_Code: E192; U/M: EA; AEC Category: Q200
signal-integrity model Resistor
simulation model Resistor
footprint 0603
footprint 0603M
footprint 0603L
footprint 0603_HV
footprint 0603S
pins: 1, 2

## RT0603DRE0712R4L
designator R?  ValueDisplayed: 12.4  (hidden comment: RT0603DRE0712R4L)
RES, 12.4, 0.5%, 0.1 W, 0603; Manufacturer: Yageo America; CompType: Resistor; Value: 12.4; Value_Code: 12R4; Tolerance_%: 0.5; Power_W: 0.1; Value2: 0.1W; VDC_V: 75; TempCo: 50 ppm/C; SizeArea_mm2: 1.28; SizeX_mm: 1.6; SizeY_mm: 0.8; SizeZ_mm: 1; EIA_Code: E192; U/M: EA; AEC Category: Q200
signal-integrity model Resistor
simulation model Resistor
footprint 0603
footprint 0603M
footprint 0603L
footprint 0603_HV
footprint 0603S
pins: 1, 2

## RT0603DRE0712R6L
designator R?  ValueDisplayed: 12.6  (hidden comment: RT0603DRE0712R6L)
RES, 12.6, 0.5%, 0.1 W, 0603; Manufacturer: Yageo America; CompType: Resistor; Value: 12.6; Value_Code: 12R6; Tolerance_%: 0.5; Power_W: 0.1; Value2: 0.1W; VDC_V: 75; TempCo: 50 ppm/C; SizeArea_mm2: 1.28; SizeX_mm: 1.6; SizeY_mm: 0.8; SizeZ_mm: 1; EIA_Code: E192; U/M: EA; AEC Category: Q200
signal-integrity model Resistor
simulation model Resistor
footprint 0603
footprint 0603M
footprint 0603L
footprint 0603_HV
footprint 0603S
pins: 1, 2

## RT0603DRE0712R7L
designator R?  ValueDisplayed: 12.7  (hidden comment: RT0603DRE0712R7L)
RES, 12.7, 0.5%, 0.1 W, 0603; Manufacturer: Yageo America; CompType: Resistor; Value: 12.7; Value_Code: 12R7; Tolerance_%: 0.5; Power_W: 0.1; Value2: 0.1W; VDC_V: 75; TempCo: 50 ppm/C; SizeArea_mm2: 1.28; SizeX_mm: 1.6; SizeY_mm: 0.8; SizeZ_mm: 1; EIA_Code: E192; U/M: EA; AEC Category: Q200
signal-integrity model Resistor
simulation model Resistor
footprint 0603
footprint 0603M
footprint 0603L
footprint 0603_HV
footprint 0603S
pins: 1, 2

## RT0603DRE0712R9L
designator R?  ValueDisplayed: 12.9  (hidden comment: RT0603DRE0712R9L)
RES, 12.9, 0.5%, 0.1 W, 0603; Manufacturer: Yageo America; CompType: Resistor; Value: 12.9; Value_Code: 12R9; Tolerance_%: 0.5; Power_W: 0.1; Value2: 0.1W; VDC_V: 75; TempCo: 50 ppm/C; SizeArea_mm2: 1.28; SizeX_mm: 1.6; SizeY_mm: 0.8; SizeZ_mm: 1; EIA_Code: E192; U/M: EA; AEC Category: Q200
signal-integrity model Resistor
simulation model Resistor
footprint 0603
footprint 0603M
footprint 0603L
footprint 0603_HV
footprint 0603S
pins: 1, 2

## RT0603DRE0712RL
designator R?  ValueDisplayed: 12.0  (hidden comment: RT0603DRE0712RL)
RES, 12.0, 0.5%, 0.1 W, 0603; Manufacturer: Yageo America; CompType: Resistor; Value: 12.0; Res_ohm: 12; Value_Code: 12R0; Tolerance_%: 0.5; Power_W: 0.1; Value2: 0.1W; VDC_V: 75; TempCo: 50 ppm/C; SizeArea_mm2: 1.28; SizeX_mm: 1.6; SizeY_mm: 0.8; SizeZ_mm: 1; EIA_Code: E192; U/M: EA; AEC Category: Q200
signal-integrity model Resistor
simulation model Resistor
footprint 0603
footprint 0603M
footprint 0603L
footprint 0603_HV
footprint 0603S
pins: 1, 2

## RT0603DRE0713K2L
designator R?  ValueDisplayed: 13.2k  (hidden comment: RT0603DRE0713K2L)
RES, 13.2 k, 0.5%, 0.1 W, 0603; Manufacturer: Yageo America; CompType: Resistor; Value: 13.2k; Res_ohm: 13200; Value_Code: 13k2; Tolerance_%: 0.5; Power_W: 0.1; Value2: 0.1W; VDC_V: 75; TempCo: 50 ppm/C; SizeArea_mm2: 1.28; SizeX_mm: 1.6; SizeY_mm: 0.8; SizeZ_mm: 1; EIA_Code: E192; U/M: EA; AEC Category: Q200
signal-integrity model Resistor
simulation model Resistor
footprint 0603
footprint 0603M
footprint 0603L
footprint 0603_HV
footprint 0603S
pins: 1, 2

## RT0603DRE0713K3L
designator R?  ValueDisplayed: 13.3k  (hidden comment: RT0603DRE0713K3L)
RES, 13.3 k, 0.5%, 0.1 W, 0603; Manufacturer: Yageo America; CompType: Resistor; Value: 13.3k; Res_ohm: 13300; Value_Code: 13k3; Tolerance_%: 0.5; Power_W: 0.1; Value2: 0.1W; VDC_V: 75; TempCo: 50 ppm/C; SizeArea_mm2: 1.28; SizeX_mm: 1.6; SizeY_mm: 0.8; SizeZ_mm: 1; EIA_Code: E192; U/M: EA; AEC Category: Q200
signal-integrity model Resistor
simulation model Resistor
footprint 0603
footprint 0603M
footprint 0603L
footprint 0603_HV
footprint 0603S
pins: 1, 2

## RT0603DRE0713K5L
designator R?  ValueDisplayed: 13.5k  (hidden comment: RT0603DRE0713K5L)
RES, 13.5 k, 0.5%, 0.1 W, 0603; Manufacturer: Yageo America; CompType: Resistor; Value: 13.5k; Res_ohm: 13500; Value_Code: 13k5; Tolerance_%: 0.5; Power_W: 0.1; Value2: 0.1W; VDC_V: 75; TempCo: 50 ppm/C; SizeArea_mm2: 1.28; SizeX_mm: 1.6; SizeY_mm: 0.8; SizeZ_mm: 1; EIA_Code: E192; U/M: EA; AEC Category: Q200
signal-integrity model Resistor
simulation model Resistor
footprint 0603
footprint 0603M
footprint 0603L
footprint 0603_HV
footprint 0603S
pins: 1, 2

## RT0603DRE0713K7L
designator R?  ValueDisplayed: 13.7k  (hidden comment: RT0603DRE0713K7L)
RES, 13.7 k, 0.5%, 0.1 W, 0603; Manufacturer: Yageo America; CompType: Resistor; Value: 13.7k; Res_ohm: 13700; Value_Code: 13k7; Tolerance_%: 0.5; Power_W: 0.1; Value2: 0.1W; VDC_V: 75; TempCo: 50 ppm/C; SizeArea_mm2: 1.28; SizeX_mm: 1.6; SizeY_mm: 0.8; SizeZ_mm: 1; EIA_Code: E192; U/M: EA; AEC Category: Q200
signal-integrity model Resistor
simulation model Resistor
footprint 0603
footprint 0603M
footprint 0603L
footprint 0603_HV
footprint 0603S
pins: 1, 2

## RT0603DRE0713K8L
designator R?  ValueDisplayed: 13.8k  (hidden comment: RT0603DRE0713K8L)
RES, 13.8 k, 0.5%, 0.1 W, 0603; Manufacturer: Yageo America; CompType: Resistor; Value: 13.8k; Res_ohm: 13800; Value_Code: 13k8; Tolerance_%: 0.5; Power_W: 0.1; Value2: 0.1W; VDC_V: 75; TempCo: 50 ppm/C; SizeArea_mm2: 1.28; SizeX_mm: 1.6; SizeY_mm: 0.8; SizeZ_mm: 1; EIA_Code: E192; U/M: EA; AEC Category: Q200
signal-integrity model Resistor
simulation model Resistor
footprint 0603
footprint 0603M
footprint 0603L
footprint 0603_HV
footprint 0603S
pins: 1, 2

## RT0603DRE0713KL
designator R?  ValueDisplayed: 13.0k  (hidden comment: RT0603DRE0713KL)
RES, 13.0 k, 0.5%, 0.1 W, 0603; Manufacturer: Yageo America; CompType: Resistor; Value: 13.0k; Res_ohm: 13000; Value_Code: 13k0; Tolerance_%: 0.5; Power_W: 0.1; Value2: 0.1W; VDC_V: 75; TempCo: 50 ppm/C; SizeArea_mm2: 1.28; SizeX_mm: 1.6; SizeY_mm: 0.8; SizeZ_mm: 1; EIA_Code: E192; U/M: EA; AEC Category: Q200
signal-integrity model Resistor
simulation model Resistor
footprint 0603
footprint 0603M
footprint 0603L
footprint 0603_HV
footprint 0603S
pins: 1, 2

## RT0603DRE0713R2L
designator R?  ValueDisplayed: 13.2  (hidden comment: RT0603DRE0713R2L)
RES, 13.2, 0.5%, 0.1 W, 0603; Manufacturer: Yageo America; CompType: Resistor; Value: 13.2; Value_Code: 13R2; Tolerance_%: 0.5; Power_W: 0.1; Value2: 0.1W; VDC_V: 75; TempCo: 50 ppm/C; SizeArea_mm2: 1.28; SizeX_mm: 1.6; SizeY_mm: 0.8; SizeZ_mm: 1; EIA_Code: E192; U/M: EA; AEC Category: Q200
signal-integrity model Resistor
simulation model Resistor
footprint 0603
footprint 0603M
footprint 0603L
footprint 0603_HV
footprint 0603S
pins: 1, 2

## RT0603DRE0713R3L
designator R?  ValueDisplayed: 13.3  (hidden comment: RT0603DRE0713R3L)
RES, 13.3, 0.5%, 0.1 W, 0603; Manufacturer: Yageo America; CompType: Resistor; Value: 13.3; Value_Code: 13R3; Tolerance_%: 0.5; Power_W: 0.1; Value2: 0.1W; VDC_V: 75; TempCo: 50 ppm/C; SizeArea_mm2: 1.28; SizeX_mm: 1.6; SizeY_mm: 0.8; SizeZ_mm: 1; EIA_Code: E192; U/M: EA; AEC Category: Q200
signal-integrity model Resistor
simulation model Resistor
footprint 0603
footprint 0603M
footprint 0603L
footprint 0603_HV
footprint 0603S
pins: 1, 2

## RT0603DRE0713R5L
designator R?  ValueDisplayed: 13.5  (hidden comment: RT0603DRE0713R5L)
RES, 13.5, 0.5%, 0.1 W, 0603; Manufacturer: Yageo America; CompType: Resistor; Value: 13.5; Value_Code: 13R5; Tolerance_%: 0.5; Power_W: 0.1; Value2: 0.1W; VDC_V: 75; TempCo: 50 ppm/C; SizeArea_mm2: 1.28; SizeX_mm: 1.6; SizeY_mm: 0.8; SizeZ_mm: 1; EIA_Code: E192; U/M: EA; AEC Category: Q200
signal-integrity model Resistor
simulation model Resistor
footprint 0603
footprint 0603M
footprint 0603L
footprint 0603_HV
footprint 0603S
pins: 1, 2

## RT0603DRE0713R7L
designator R?  ValueDisplayed: 13.7  (hidden comment: RT0603DRE0713R7L)
RES, 13.7, 0.5%, 0.1 W, 0603; Manufacturer: Yageo America; CompType: Resistor; Value: 13.7; Value_Code: 13R7; Tolerance_%: 0.5; Power_W: 0.1; Value2: 0.1W; VDC_V: 75; TempCo: 50 ppm/C; SizeArea_mm2: 1.28; SizeX_mm: 1.6; SizeY_mm: 0.8; SizeZ_mm: 1; EIA_Code: E192; U/M: EA; AEC Category: Q200
signal-integrity model Resistor
simulation model Resistor
footprint 0603
footprint 0603M
footprint 0603L
footprint 0603_HV
footprint 0603S
pins: 1, 2

## RT0603DRE0713R8L
designator R?  ValueDisplayed: 13.8  (hidden comment: RT0603DRE0713R8L)
RES, 13.8, 0.5%, 0.1 W, 0603; Manufacturer: Yageo America; CompType: Resistor; Value: 13.8; Value_Code: 13R8; Tolerance_%: 0.5; Power_W: 0.1; Value2: 0.1W; VDC_V: 75; TempCo: 50 ppm/C; SizeArea_mm2: 1.28; SizeX_mm: 1.6; SizeY_mm: 0.8; SizeZ_mm: 1; EIA_Code: E192; U/M: EA; AEC Category: Q200
signal-integrity model Resistor
simulation model Resistor
footprint 0603
footprint 0603M
footprint 0603L
footprint 0603_HV
footprint 0603S
pins: 1, 2

## RT0603DRE0713RL
designator R?  ValueDisplayed: 13.0  (hidden comment: RT0603DRE0713RL)
RES, 13.0, 0.5%, 0.1 W, 0603; Manufacturer: Yageo America; CompType: Resistor; Value: 13.0; Res_ohm: 13; Value_Code: 13R0; Tolerance_%: 0.5; Power_W: 0.1; Value2: 0.1W; VDC_V: 75; TempCo: 50 ppm/C; SizeArea_mm2: 1.28; SizeX_mm: 1.6; SizeY_mm: 0.8; SizeZ_mm: 1; EIA_Code: E192; U/M: EA; AEC Category: Q200
signal-integrity model Resistor
simulation model Resistor
footprint 0603
footprint 0603M
footprint 0603L
footprint 0603_HV
footprint 0603S
pins: 1, 2

## RT0603DRE0714K2L
designator R?  ValueDisplayed: 14.2k  (hidden comment: RT0603DRE0714K2L)
RES, 14.2 k, 0.5%, 0.1 W, 0603; Manufacturer: Yageo America; CompType: Resistor; Value: 14.2k; Res_ohm: 14200; Value_Code: 14k2; Tolerance_%: 0.5; Power_W: 0.1; Value2: 0.1W; VDC_V: 75; TempCo: 50 ppm/C; SizeArea_mm2: 1.28; SizeX_mm: 1.6; SizeY_mm: 0.8; SizeZ_mm: 1; EIA_Code: E192; U/M: EA; AEC Category: Q200
signal-integrity model Resistor
simulation model Resistor
footprint 0603
footprint 0603M
footprint 0603L
footprint 0603_HV
footprint 0603S
pins: 1, 2

## RT0603DRE0714K3L
designator R?  ValueDisplayed: 14.3k  (hidden comment: RT0603DRE0714K3L)
RES, 14.3 k, 0.5%, 0.1 W, 0603; Manufacturer: Yageo America; CompType: Resistor; Value: 14.3k; Res_ohm: 14300; Value_Code: 14k3; Tolerance_%: 0.5; Power_W: 0.1; Value2: 0.1W; VDC_V: 75; TempCo: 50 ppm/C; SizeArea_mm2: 1.28; SizeX_mm: 1.6; SizeY_mm: 0.8; SizeZ_mm: 1; EIA_Code: E192; U/M: EA; AEC Category: Q200
signal-integrity model Resistor
simulation model Resistor
footprint 0603
footprint 0603M
footprint 0603L
footprint 0603_HV
footprint 0603S
pins: 1, 2

## RT0603DRE0714K5L
designator R?  ValueDisplayed: 14.5k  (hidden comment: RT0603DRE0714K5L)
RES, 14.5 k, 0.5%, 0.1 W, 0603; Manufacturer: Yageo America; CompType: Resistor; Value: 14.5k; Res_ohm: 14500; Value_Code: 14k5; Tolerance_%: 0.5; Power_W: 0.1; Value2: 0.1W; VDC_V: 75; TempCo: 50 ppm/C; SizeArea_mm2: 1.28; SizeX_mm: 1.6; SizeY_mm: 0.8; SizeZ_mm: 1; EIA_Code: E192; U/M: EA; AEC Category: Q200
signal-integrity model Resistor
simulation model Resistor
footprint 0603
footprint 0603M
footprint 0603L
footprint 0603_HV
footprint 0603S
pins: 1, 2

## RT0603DRE0714K7L
designator R?  ValueDisplayed: 14.7k  (hidden comment: RT0603DRE0714K7L)
RES, 14.7 k, 0.5%, 0.1 W, 0603; Manufacturer: Yageo America; CompType: Resistor; Value: 14.7k; Res_ohm: 14700; Value_Code: 14k7; Tolerance_%: 0.5; Power_W: 0.1; Value2: 0.1W; VDC_V: 75; TempCo: 50 ppm/C; SizeArea_mm2: 1.28; SizeX_mm: 1.6; SizeY_mm: 0.8; SizeZ_mm: 1; EIA_Code: E192; U/M: EA; AEC Category: Q200
signal-integrity model Resistor
simulation model Resistor
footprint 0603
footprint 0603M
footprint 0603L
footprint 0603_HV
footprint 0603S
pins: 1, 2

## RT0603DRE0714K9L
designator R?  ValueDisplayed: 14.9k  (hidden comment: RT0603DRE0714K9L)
RES, 14.9 k, 0.5%, 0.1 W, 0603; Manufacturer: Yageo America; CompType: Resistor; Value: 14.9k; Res_ohm: 14900; Value_Code: 14k9; Tolerance_%: 0.5; Power_W: 0.1; Value2: 0.1W; VDC_V: 75; TempCo: 50 ppm/C; SizeArea_mm2: 1.28; SizeX_mm: 1.6; SizeY_mm: 0.8; SizeZ_mm: 1; EIA_Code: E192; U/M: EA; AEC Category: Q200
signal-integrity model Resistor
simulation model Resistor
footprint 0603
footprint 0603M
footprint 0603L
footprint 0603_HV
footprint 0603S
pins: 1, 2

## RT0603DRE0714KL
designator R?  ValueDisplayed: 14.0k  (hidden comment: RT0603DRE0714KL)
RES, 14.0 k, 0.5%, 0.1 W, 0603; Manufacturer: Yageo America; CompType: Resistor; Value: 14.0k; Res_ohm: 14000; Value_Code: 14k0; Tolerance_%: 0.5; Power_W: 0.1; Value2: 0.1W; VDC_V: 75; TempCo: 50 ppm/C; SizeArea_mm2: 1.28; SizeX_mm: 1.6; SizeY_mm: 0.8; SizeZ_mm: 1; EIA_Code: E192; U/M: EA; AEC Category: Q200
signal-integrity model Resistor
simulation model Resistor
footprint 0603
footprint 0603M
footprint 0603L
footprint 0603_HV
footprint 0603S
pins: 1, 2

## RT0603DRE0714R2L
designator R?  ValueDisplayed: 14.2  (hidden comment: RT0603DRE0714R2L)
RES, 14.2, 0.5%, 0.1 W, 0603; Manufacturer: Yageo America; CompType: Resistor; Value: 14.2; Value_Code: 14R2; Tolerance_%: 0.5; Power_W: 0.1; Value2: 0.1W; VDC_V: 75; TempCo: 50 ppm/C; SizeArea_mm2: 1.28; SizeX_mm: 1.6; SizeY_mm: 0.8; SizeZ_mm: 1; EIA_Code: E192; U/M: EA; AEC Category: Q200
signal-integrity model Resistor
simulation model Resistor
footprint 0603
footprint 0603M
footprint 0603L
footprint 0603_HV
footprint 0603S
pins: 1, 2

## RT0603DRE0714R3L
designator R?  ValueDisplayed: 14.3  (hidden comment: RT0603DRE0714R3L)
RES, 14.3, 0.5%, 0.1 W, 0603; Manufacturer: Yageo America; CompType: Resistor; Value: 14.3; Value_Code: 14R3; Tolerance_%: 0.5; Power_W: 0.1; Value2: 0.1W; VDC_V: 75; TempCo: 50 ppm/C; SizeArea_mm2: 1.28; SizeX_mm: 1.6; SizeY_mm: 0.8; SizeZ_mm: 1; EIA_Code: E192; U/M: EA; AEC Category: Q200
signal-integrity model Resistor
simulation model Resistor
footprint 0603
footprint 0603M
footprint 0603L
footprint 0603_HV
footprint 0603S
pins: 1, 2

## RT0603DRE0714R5L
designator R?  ValueDisplayed: 14.5  (hidden comment: RT0603DRE0714R5L)
RES, 14.5, 0.5%, 0.1 W, 0603; Manufacturer: Yageo America; CompType: Resistor; Value: 14.5; Value_Code: 14R5; Tolerance_%: 0.5; Power_W: 0.1; Value2: 0.1W; VDC_V: 75; TempCo: 50 ppm/C; SizeArea_mm2: 1.28; SizeX_mm: 1.6; SizeY_mm: 0.8; SizeZ_mm: 1; EIA_Code: E192; U/M: EA; AEC Category: Q200
signal-integrity model Resistor
simulation model Resistor
footprint 0603
footprint 0603M
footprint 0603L
footprint 0603_HV
footprint 0603S
pins: 1, 2

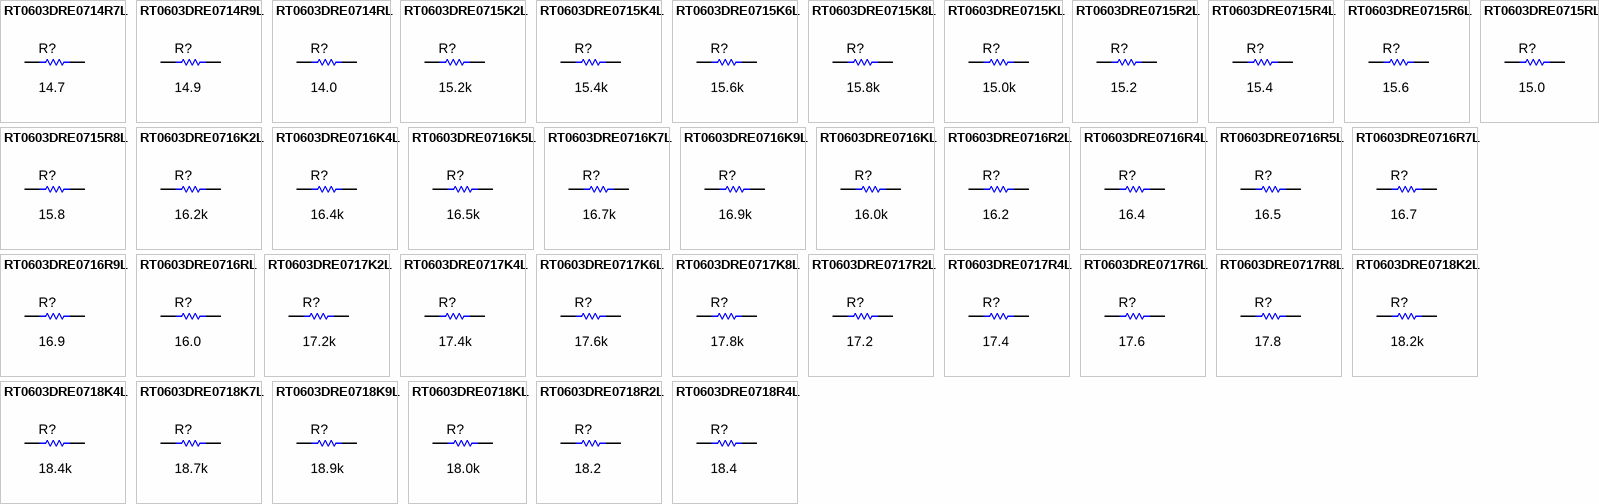
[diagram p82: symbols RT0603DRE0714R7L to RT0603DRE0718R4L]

## RT0603DRE0714R7L
designator R?  ValueDisplayed: 14.7  (hidden comment: RT0603DRE0714R7L)
RES, 14.7, 0.5%, 0.1 W, 0603; Manufacturer: Yageo America; CompType: Resistor; Value: 14.7; Value_Code: 14R7; Tolerance_%: 0.5; Power_W: 0.1; Value2: 0.1W; VDC_V: 75; TempCo: 50 ppm/C; SizeArea_mm2: 1.28; SizeX_mm: 1.6; SizeY_mm: 0.8; SizeZ_mm: 1; EIA_Code: E192; U/M: EA; AEC Category: Q200
signal-integrity model Resistor
simulation model Resistor
footprint 0603
footprint 0603M
footprint 0603L
footprint 0603_HV
footprint 0603S
pins: 1, 2

## RT0603DRE0714R9L
designator R?  ValueDisplayed: 14.9  (hidden comment: RT0603DRE0714R9L)
RES, 14.9, 0.5%, 0.1 W, 0603; Manufacturer: Yageo America; CompType: Resistor; Value: 14.9; Value_Code: 14R9; Tolerance_%: 0.5; Power_W: 0.1; Value2: 0.1W; VDC_V: 75; TempCo: 50 ppm/C; SizeArea_mm2: 1.28; SizeX_mm: 1.6; SizeY_mm: 0.8; SizeZ_mm: 1; EIA_Code: E192; U/M: EA; AEC Category: Q200
signal-integrity model Resistor
simulation model Resistor
footprint 0603
footprint 0603M
footprint 0603L
footprint 0603_HV
footprint 0603S
pins: 1, 2

## RT0603DRE0714RL
designator R?  ValueDisplayed: 14.0  (hidden comment: RT0603DRE0714RL)
RES, 14.0, 0.5%, 0.1 W, 0603; Manufacturer: Yageo America; CompType: Resistor; Value: 14.0; Res_ohm: 14; Value_Code: 14R0; Tolerance_%: 0.5; Power_W: 0.1; Value2: 0.1W; VDC_V: 75; TempCo: 50 ppm/C; SizeArea_mm2: 1.28; SizeX_mm: 1.6; SizeY_mm: 0.8; SizeZ_mm: 1; EIA_Code: E192; U/M: EA; AEC Category: Q200
signal-integrity model Resistor
simulation model Resistor
footprint 0603
footprint 0603M
footprint 0603L
footprint 0603_HV
footprint 0603S
pins: 1, 2

## RT0603DRE0715K2L
designator R?  ValueDisplayed: 15.2k  (hidden comment: RT0603DRE0715K2L)
RES, 15.2 k, 0.5%, 0.1 W, 0603; Manufacturer: Yageo America; CompType: Resistor; Value: 15.2k; Res_ohm: 15200; Value_Code: 15k2; Tolerance_%: 0.5; Power_W: 0.1; Value2: 0.1W; VDC_V: 75; TempCo: 50 ppm/C; SizeArea_mm2: 1.28; SizeX_mm: 1.6; SizeY_mm: 0.8; SizeZ_mm: 1; EIA_Code: E192; U/M: EA; AEC Category: Q200
signal-integrity model Resistor
simulation model Resistor
footprint 0603
footprint 0603M
footprint 0603L
footprint 0603_HV
footprint 0603S
pins: 1, 2

## RT0603DRE0715K4L
designator R?  ValueDisplayed: 15.4k  (hidden comment: RT0603DRE0715K4L)
RES, 15.4 k, 0.5%, 0.1 W, 0603; Manufacturer: Yageo America; CompType: Resistor; Value: 15.4k; Res_ohm: 15400; Value_Code: 15k4; Tolerance_%: 0.5; Power_W: 0.1; Value2: 0.1W; VDC_V: 75; TempCo: 50 ppm/C; SizeArea_mm2: 1.28; SizeX_mm: 1.6; SizeY_mm: 0.8; SizeZ_mm: 1; EIA_Code: E192; U/M: EA; AEC Category: Q200
signal-integrity model Resistor
simulation model Resistor
footprint 0603
footprint 0603M
footprint 0603L
footprint 0603_HV
footprint 0603S
pins: 1, 2

## RT0603DRE0715K6L
designator R?  ValueDisplayed: 15.6k  (hidden comment: RT0603DRE0715K6L)
RES, 15.6 k, 0.5%, 0.1 W, 0603; Manufacturer: Yageo America; CompType: Resistor; Value: 15.6k; Res_ohm: 15600; Value_Code: 15k6; Tolerance_%: 0.5; Power_W: 0.1; Value2: 0.1W; VDC_V: 75; TempCo: 50 ppm/C; SizeArea_mm2: 1.28; SizeX_mm: 1.6; SizeY_mm: 0.8; SizeZ_mm: 1; EIA_Code: E192; U/M: EA; AEC Category: Q200
signal-integrity model Resistor
simulation model Resistor
footprint 0603
footprint 0603M
footprint 0603L
footprint 0603_HV
footprint 0603S
pins: 1, 2

## RT0603DRE0715K8L
designator R?  ValueDisplayed: 15.8k  (hidden comment: RT0603DRE0715K8L)
RES, 15.8 k, 0.5%, 0.1 W, 0603; Manufacturer: Yageo America; CompType: Resistor; Value: 15.8k; Res_ohm: 15800; Value_Code: 15k8; Tolerance_%: 0.5; Power_W: 0.1; Value2: 0.1W; VDC_V: 75; TempCo: 50 ppm/C; SizeArea_mm2: 1.28; SizeX_mm: 1.6; SizeY_mm: 0.8; SizeZ_mm: 1; EIA_Code: E192; U/M: EA; AEC Category: Q200
signal-integrity model Resistor
simulation model Resistor
footprint 0603
footprint 0603M
footprint 0603L
footprint 0603_HV
footprint 0603S
pins: 1, 2

## RT0603DRE0715KL
designator R?  ValueDisplayed: 15.0k  (hidden comment: RT0603DRE0715KL)
RES, 15.0 k, 0.5%, 0.1 W, 0603; Manufacturer: Yageo America; CompType: Resistor; Value: 15.0k; Res_ohm: 15000; Value_Code: 15k0; Tolerance_%: 0.5; Power_W: 0.1; Value2: 0.1W; VDC_V: 75; TempCo: 50 ppm/C; SizeArea_mm2: 1.28; SizeX_mm: 1.6; SizeY_mm: 0.8; SizeZ_mm: 1; EIA_Code: E192; U/M: EA; AEC Category: Q200
signal-integrity model Resistor
simulation model Resistor
footprint 0603
footprint 0603M
footprint 0603L
footprint 0603_HV
footprint 0603S
pins: 1, 2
